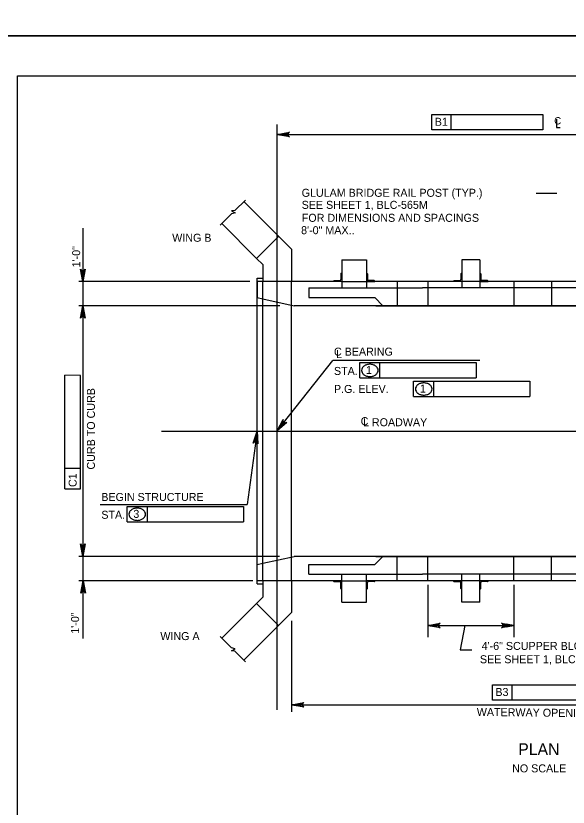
# Model space of a CAD drawing. Extents: x 638263 to 640391, y 293683 to 298655.
# Drawn here: x 638474.9 to 638681.9, y 297552.4 to 297849 of the extents above; entities that cross this region are included whole.
import ezdxf

# ---------------------------------------------------------------- set-up
doc = ezdxf.new("R2010")
doc.units = 0
for name, color, linetype in [('2', 7, 'Continuous'), ('3', 7, 'Continuous'), ('4', 7, 'Continuous'), ('PLT-BNDY', 7, 'Continuous')]:
    doc.layers.add(name, color=color, linetype=linetype)

msp = doc.modelspace()

# ---------------------------------------------------------------- linework, layer by layer
at = {"layer": '2'}
for p, q in [((638475.46, 297262.46), (638475.46, 297826.46)), ((638475.46, 297826.46), (639261.46, 297826.46)), ((638578.21, 297761.45), (638560.35, 297779.32)), ((638565.14, 297758.06), (638552.12, 297771.09)), ((638565.14, 297758.06), (638573.37, 297766.29)), ((638578.21, 297761.45), (638578.21, 297749.36)), ((638567.45, 297755.76), (638565.14, 297758.06)), ((638567.45, 297755.76), (638567.45, 297749.36)), ((638597.06, 297757.45), (638606.3, 297757.45)), ((638597.06, 297757.45), (638597.06, 297746.97)), ((638606.3, 297757.45), (638606.3, 297746.97)), ((638648.78, 297757.45), (638642.06, 297757.45)), ((638642.06, 297757.45), (638642.06, 297746.97)), ((638648.78, 297757.45), (638648.78, 297746.97)), ((638596.7, 297752.27), (638596.7, 297750.09)), ((638596.88, 297752.45), (638597.06, 297752.45)), ((638597.06, 297752.45), (638597.06, 297749.36)), ((638606.48, 297752.45), (638606.3, 297752.45)), ((638606.3, 297752.45), (638606.3, 297749.36)), ((638606.66, 297752.27), (638606.66, 297750.09)), ((638641.69, 297752.27), (638641.69, 297750.09)), ((638641.87, 297752.45), (638642.06, 297752.45)), ((638642.06, 297752.45), (638642.06, 297749.36)), ((638648.97, 297752.45), (638648.78, 297752.45)), ((638648.78, 297752.45), (638648.78, 297749.36)), ((638649.15, 297752.27), (638649.15, 297750.09)), ((638565.32, 297636.1), (638565.32, 297750.67)), ((638565.32, 297750.67), (638567.45, 297750.67)), ((638565.32, 297749.36), (638565.32, 297743.33)), ((638597.06, 297749.36), (638565.32, 297749.36)), ((638567.45, 297637.25), (638567.45, 297749.36)), ((638578.21, 297637.25), (638578.21, 297749.36)), ((638593.97, 297749.54), (638593.97, 297749.36)), ((638597.06, 297749.36), (638593.97, 297749.36)), ((638594.15, 297749.73), (638596.33, 297749.73)), ((638597.06, 297749.36), (638606.3, 297749.36)), ((638606.3, 297749.36), (638609.39, 297749.36)), ((638642.06, 297749.36), (638606.3, 297749.36)), ((638609.21, 297749.73), (638607.03, 297749.73)), ((638609.39, 297749.54), (638609.39, 297749.36)), ((638617.85, 297749.36), (638617.85, 297740.24)), ((638629.25, 297749.36), (638629.25, 297740.24)), ((638638.97, 297749.54), (638638.97, 297749.36)), ((638642.06, 297749.36), (638638.97, 297749.36)), ((638639.15, 297749.73), (638641.33, 297749.73)), ((638648.78, 297749.36), (638642.06, 297749.36)), ((638648.78, 297749.36), (638651.87, 297749.36)), ((638687.21, 297749.36), (638648.78, 297749.36)), ((638651.69, 297749.73), (638649.51, 297749.73)), ((638651.87, 297749.54), (638651.87, 297749.36)), ((638661.59, 297749.36), (638661.59, 297740.24)), ((638675.61, 297749.36), (638675.61, 297740.24)), ((638584.74, 297746.97), (638627.24, 297746.97)), ((638584.74, 297746.97), (638584.74, 297743.33)), ((638757.1, 297746.97), (638627.24, 297746.97)), ((638565.32, 297743.33), (638567.49, 297742.85)), ((638584.74, 297743.33), (638609.38, 297743.33)), ((638612.47, 297740.24), (638609.38, 297743.33)), ((638567.49, 297742.85), (638579.17, 297740.24)), ((638612.47, 297740.24), (638579.17, 297740.24)), ((638609.8, 297740.24), (638625.96, 297740.24)), ((638609.8, 297740.24), (638762.67, 297740.24)), ((638729.37, 297740.24), (638612.47, 297740.24)), ((638567.49, 297643.76), (638579.17, 297646.37)), ((638612.47, 297646.37), (638579.17, 297646.37)), ((638612.47, 297646.37), (638609.38, 297643.28)), ((638609.8, 297646.37), (638625.96, 297646.37)), ((638609.8, 297646.37), (638762.67, 297646.37)), ((638729.37, 297646.37), (638612.47, 297646.37)), ((638617.85, 297637.25), (638617.85, 297646.37)), ((638629.25, 297637.25), (638629.25, 297646.37)), ((638661.59, 297637.25), (638661.59, 297646.37)), ((638675.61, 297637.25), (638675.61, 297646.37)), ((638565.32, 297643.28), (638567.49, 297643.76)), ((638565.32, 297637.25), (638565.32, 297643.28)), ((638584.74, 297643.28), (638609.38, 297643.28)), ((638584.74, 297639.64), (638584.74, 297643.28)), ((638584.74, 297639.64), (638627.24, 297639.64)), ((638597.06, 297629.16), (638597.06, 297639.64)), ((638606.3, 297629.16), (638606.3, 297639.64)), ((638757.1, 297639.64), (638627.24, 297639.64)), ((638642.06, 297629.16), (638642.06, 297639.64)), ((638648.78, 297629.16), (638648.78, 297639.64)), ((638597.06, 297637.25), (638565.32, 297637.25)), ((638567.45, 297637.25), (638567.45, 297631.03)), ((638578.21, 297637.25), (638578.21, 297625.33)), ((638593.97, 297637.07), (638593.97, 297637.25)), ((638597.06, 297637.25), (638593.97, 297637.25)), ((638594.15, 297636.89), (638596.33, 297636.89)), ((638596.7, 297634.34), (638596.7, 297636.52)), ((638597.06, 297637.25), (638606.3, 297637.25)), ((638597.06, 297634.16), (638597.06, 297637.25)), ((638606.3, 297634.16), (638606.3, 297637.25)), ((638606.3, 297637.25), (638609.39, 297637.25)), ((638642.06, 297637.25), (638606.3, 297637.25)), ((638606.66, 297634.34), (638606.66, 297636.52)), ((638609.21, 297636.89), (638607.03, 297636.89)), ((638609.39, 297637.07), (638609.39, 297637.25)), ((638638.97, 297637.07), (638638.97, 297637.25)), ((638642.06, 297637.25), (638638.97, 297637.25)), ((638639.15, 297636.89), (638641.33, 297636.89)), ((638641.69, 297634.34), (638641.69, 297636.52)), ((638642.06, 297634.16), (638642.06, 297637.25)), ((638648.78, 297637.25), (638642.06, 297637.25)), ((638648.78, 297634.16), (638648.78, 297637.25)), ((638648.78, 297637.25), (638651.87, 297637.25)), ((638687.21, 297637.25), (638648.78, 297637.25)), ((638649.15, 297634.34), (638649.15, 297636.52)), ((638651.69, 297636.89), (638649.51, 297636.89)), ((638651.87, 297637.07), (638651.87, 297637.25)), ((638565.32, 297636.1), (638567.45, 297636.1)), ((638596.88, 297634.16), (638597.06, 297634.16)), ((638606.48, 297634.16), (638606.3, 297634.16)), ((638641.87, 297634.16), (638642.06, 297634.16)), ((638648.97, 297634.16), (638648.78, 297634.16)), ((638567.45, 297631.03), (638565.14, 297628.72)), ((638565.14, 297628.72), (638552.12, 297615.7)), ((638565.14, 297628.72), (638573.37, 297620.49)), ((638597.06, 297629.16), (638606.3, 297629.16)), ((638648.78, 297629.16), (638642.06, 297629.16)), ((638578.21, 297625.33), (638560.35, 297607.47))]:
    msp.add_line(p, q, dxfattribs=at)
for centre, radius, start, end in [((638596.88, 297752.27), 0.182, 90, 179.9984), ((638606.48, 297752.27), 0.182, 0.0016, 90), ((638641.87, 297752.27), 0.182, 90, 179.9984), ((638648.97, 297752.27), 0.182, 0.0016, 90), ((638594.15, 297749.54), 0.182, 90, 179.9984), ((638596.33, 297750.09), 0.364, 270, 359.9984), ((638607.03, 297750.09), 0.364, 180.0016, 270), ((638609.21, 297749.54), 0.182, 0.0016, 90), ((638639.15, 297749.54), 0.182, 90, 179.9984), ((638641.33, 297750.09), 0.364, 270, 359.9984), ((638649.51, 297750.09), 0.364, 180.0016, 270), ((638651.69, 297749.54), 0.182, 0.0016, 90), ((638594.15, 297637.07), 0.182, 180.0016, 270), ((638596.33, 297636.52), 0.364, 0.0016, 90), ((638607.03, 297636.52), 0.364, 90, 179.9984), ((638609.21, 297637.07), 0.182, 270, 359.9984), ((638639.15, 297637.07), 0.182, 180.0016, 270), ((638641.33, 297636.52), 0.364, 0.0016, 90), ((638649.51, 297636.52), 0.364, 90, 179.9984), ((638651.69, 297637.07), 0.182, 270, 359.9984), ((638596.88, 297634.34), 0.182, 180.0016, 270), ((638606.48, 297634.34), 0.182, 270, 359.9984), ((638641.87, 297634.34), 0.182, 180.0016, 270), ((638648.97, 297634.34), 0.182, 270, 359.9984)]:
    msp.add_arc(centre, radius, start, end, dxfattribs=at)
at = {"layer": '3'}
for p, q in [((638572.83, 297588.85), (638572.83, 297808.19)), ((638557.02, 297775.99), (638560.93, 297779.9)), ((638557.02, 297775.99), (638555.67, 297775.83)), ((638555.67, 297775.83), (638557.06, 297775.13)), ((638551.48, 297770.45), (638555.75, 297774.72)), ((638557.06, 297775.13), (638555.75, 297774.72)), ((638551.48, 297616.34), (638555.75, 297612.07)), ((638555.67, 297610.96), (638557.06, 297611.65)), ((638557.02, 297610.8), (638555.67, 297610.96)), ((638557.06, 297611.65), (638555.75, 297612.07)), ((638557.02, 297610.8), (638560.93, 297606.89))]:
    msp.add_line(p, q, dxfattribs=at)
at = {"layer": '4'}
for p, q in [((638630.83, 297811.98), (638638.06, 297811.98)), ((638630.83, 297806.21), (638630.83, 297811.98)), ((638638.06, 297806.21), (638638.06, 297811.98)), ((638638.06, 297811.98), (638672.35, 297811.98)), ((638672.35, 297811.98), (638672.35, 297806.21)), ((638677.52, 297810.26), (638677.52, 297807.07)), ((638672.35, 297806.21), (638630.83, 297806.21)), ((638677.52, 297807.07), (638678.85, 297807.07)), ((638572.83, 297804.47), (638769.01, 297804.47)), ((638669.92, 297782.54), (638677.65, 297782.54)), ((638499.98, 297769.4), (638499.98, 297615.55)), ((638562.63, 297749.36), (638498.54, 297749.36)), ((638573.85, 297740.24), (638498.54, 297740.24)), ((638572.83, 297693.42), (638593.74, 297719.75)), ((638648.82, 297719.75), (638593.74, 297719.75)), ((638603.79, 297718.99), (638611.37, 297718.99)), ((638603.79, 297713.22), (638603.79, 297718.99)), ((638611.37, 297713.22), (638611.37, 297718.99)), ((638611.37, 297718.99), (638647.38, 297718.99)), ((638647.38, 297718.99), (638647.38, 297713.22)), ((638499.15, 297714.21), (638493.24, 297714.22)), ((638493.24, 297679.26), (638493.24, 297714.22)), ((638499.15, 297671.69), (638499.15, 297714.21)), ((638603.79, 297713.22), (638647.38, 297713.22)), ((638623.98, 297706.25), (638623.98, 297712.02)), ((638623.98, 297712.02), (638631.56, 297712.02)), ((638631.56, 297706.25), (638631.56, 297712.02)), ((638631.56, 297712.02), (638667.57, 297712.02)), ((638667.57, 297712.02), (638667.57, 297706.25)), ((638623.98, 297706.25), (638667.57, 297706.25)), ((638529.5, 297693.31), (638814.51, 297693.31)), ((638565.32, 297693.31), (638561.63, 297665.85)), ((638493.24, 297671.7), (638493.24, 297679.26)), ((638499.15, 297679.25), (638493.24, 297679.26)), ((638493.24, 297671.7), (638499.15, 297671.69)), ((638506.55, 297665.85), (638561.63, 297665.85)), ((638516.6, 297659.32), (638516.6, 297665.08)), ((638516.6, 297665.08), (638524.18, 297665.08)), ((638524.18, 297659.32), (638524.18, 297665.08)), ((638524.18, 297665.08), (638560.19, 297665.08)), ((638560.19, 297665.08), (638560.19, 297659.32)), ((638516.6, 297659.32), (638560.19, 297659.32)), ((638573.69, 297646.37), (638498.54, 297646.37)), ((638563.75, 297637.25), (638498.54, 297637.25)), ((638629.25, 297635.71), (638629.25, 297616.07)), ((638661.59, 297635.71), (638661.59, 297616.07)), ((638578.21, 297622.15), (638578.21, 297588.05)), ((638629.25, 297620.5), (638661.59, 297620.5)), ((638643.2, 297620.5), (638641.36, 297611.28)), ((638641.36, 297611.28), (638645.79, 297611.28)), ((638653.55, 297592.5), (638653.56, 297598.27)), ((638653.56, 297598.27), (638660.91, 297598.27)), ((638660.9, 297592.5), (638660.91, 297598.27)), ((638660.91, 297598.27), (638695.08, 297598.25)), ((638695.08, 297592.48), (638653.55, 297592.5)), ((638578.21, 297590.75), (638763.2, 297590.75))]:
    msp.add_line(p, q, dxfattribs=at)
for points in [[(638572.83, 297804.47), (638577.49, 297805.34), (638577.13, 297805.1), (638576.95, 297804.78), (638576.89, 297804.47), (638576.95, 297804.16), (638577.13, 297803.85), (638577.49, 297803.6), (638572.83, 297804.47), (638577.13, 297803.85), (638576.95, 297804.16), (638572.83, 297804.47), (638576.89, 297804.47), (638576.95, 297804.78), (638572.83, 297804.47), (638577.13, 297805.1)], [(638499.98, 297749.36), (638499.11, 297754.02), (638499.36, 297753.67), (638499.67, 297753.48), (638499.98, 297753.43), (638500.3, 297753.48), (638500.61, 297753.67), (638500.86, 297754.02), (638499.98, 297749.36), (638500.61, 297753.67), (638500.3, 297753.48), (638499.98, 297749.36), (638499.98, 297753.43), (638499.67, 297753.48), (638499.98, 297749.36), (638499.36, 297753.67)], [(638499.98, 297740.24), (638500.86, 297735.58), (638500.61, 297735.94), (638500.3, 297736.12), (638499.98, 297736.18), (638499.67, 297736.12), (638499.36, 297735.94), (638499.11, 297735.58), (638499.98, 297740.24), (638499.36, 297735.94), (638499.67, 297736.12), (638499.98, 297740.24), (638499.98, 297736.18), (638500.3, 297736.12), (638499.98, 297740.24), (638500.61, 297735.94)], [(638572.83, 297693.42), (638575.04, 297697.61), (638575.02, 297697.17), (638575.14, 297696.83), (638575.36, 297696.6), (638575.63, 297696.45), (638575.99, 297696.4), (638576.41, 297696.52), (638572.83, 297693.42), (638575.99, 297696.4), (638575.63, 297696.45), (638572.83, 297693.42), (638575.36, 297696.6), (638575.14, 297696.83), (638572.83, 297693.42), (638575.02, 297697.17)], [(638565.32, 297693.31), (638565.56, 297688.57), (638565.36, 297688.96), (638565.08, 297689.19), (638564.78, 297689.28), (638564.46, 297689.27), (638564.13, 297689.13), (638563.83, 297688.8), (638565.32, 297693.31), (638564.13, 297689.13), (638564.46, 297689.27), (638565.32, 297693.31), (638564.78, 297689.28), (638565.08, 297689.19), (638565.32, 297693.31), (638565.36, 297688.96)], [(638499.98, 297646.37), (638499.11, 297651.03), (638499.36, 297650.67), (638499.67, 297650.48), (638499.98, 297650.43), (638500.3, 297650.48), (638500.61, 297650.67), (638500.86, 297651.03), (638499.98, 297646.37), (638500.61, 297650.67), (638500.3, 297650.48), (638499.98, 297646.37), (638499.98, 297650.43), (638499.67, 297650.48), (638499.98, 297646.37), (638499.36, 297650.67)], [(638500.09, 297637.25), (638500.97, 297632.59), (638500.72, 297632.95), (638500.41, 297633.13), (638500.09, 297633.19), (638499.78, 297633.13), (638499.47, 297632.95), (638499.22, 297632.59), (638500.09, 297637.25), (638499.47, 297632.95), (638499.78, 297633.13), (638500.09, 297637.25), (638500.09, 297633.19), (638500.41, 297633.13), (638500.09, 297637.25), (638500.72, 297632.95)], [(638629.25, 297620.5), (638633.91, 297621.38), (638633.55, 297621.13), (638633.37, 297620.82), (638633.31, 297620.5), (638633.37, 297620.19), (638633.55, 297619.88), (638633.91, 297619.63), (638629.25, 297620.5), (638633.55, 297619.88), (638633.37, 297620.19), (638629.25, 297620.5), (638633.31, 297620.5), (638633.37, 297620.82), (638629.25, 297620.5), (638633.55, 297621.13)], [(638661.59, 297620.5), (638656.93, 297619.63), (638657.29, 297619.88), (638657.47, 297620.19), (638657.53, 297620.5), (638657.47, 297620.82), (638657.29, 297621.13), (638656.93, 297621.38), (638661.59, 297620.5), (638657.29, 297621.13), (638657.47, 297620.82), (638661.59, 297620.5), (638657.53, 297620.5), (638657.47, 297620.19), (638661.59, 297620.5), (638657.29, 297619.88)], [(638578.21, 297590.75), (638582.87, 297591.62), (638582.52, 297591.38), (638582.33, 297591.06), (638582.28, 297590.75), (638582.33, 297590.44), (638582.52, 297590.13), (638582.87, 297589.88), (638578.21, 297590.75), (638582.52, 297590.13), (638582.33, 297590.44), (638578.21, 297590.75), (638582.28, 297590.75), (638582.33, 297591.06), (638578.21, 297590.75), (638582.52, 297591.38)]]:
    msp.add_lwpolyline(points, dxfattribs=at)
for points in [[(638499.5, 297752.25), (638500.46, 297752.25), (638499.98, 297749.36)], [(638499.5, 297737.36), (638500.46, 297737.36), (638499.98, 297740.24)], [(638499.5, 297649.25), (638500.46, 297649.25), (638499.98, 297646.37)], [(638499.5, 297634.38), (638500.46, 297634.38), (638499.98, 297637.26)], [(638632.2, 297621), (638632.2, 297620.01), (638629.25, 297620.5)], [(638658.64, 297621), (638658.64, 297620.01), (638661.59, 297620.5)]]:
    msp.add_lwpolyline(points, close=True, dxfattribs=at)
for centre, radius, start, end in [((638606.17, 297716.06), 1.71, 150.6308, 180), ((638606.85, 297715.68), 2.49, 126.3544, 150.6308), ((638607.29, 297715.08), 3.23, 106.9552, 126.3544), ((638607.58, 297714.13), 4.22, 90, 106.9552), ((638607.58, 297714.13), 4.22, 73.0448, 90), ((638607.87, 297715.08), 3.23, 53.6456, 73.0448), ((638608.31, 297715.68), 2.49, 29.3692, 53.6456), ((638608.99, 297716.06), 1.71, 0, 29.3692), ((638606.17, 297716.06), 1.71, 180, 209.3692), ((638606.85, 297716.44), 2.49, 209.3692, 233.6456), ((638607.29, 297717.04), 3.23, 233.6456, 253.0448), ((638607.58, 297717.98), 4.22, 253.0448, 270), ((638607.58, 297717.98), 4.22, 270, 286.9552), ((638607.87, 297717.04), 3.23, 286.9552, 306.3544), ((638608.31, 297716.44), 2.49, 306.3544, 330.6308), ((638608.99, 297716.06), 1.71, 330.6308, 0), ((638627.04, 297708.71), 2.49, 126.3544, 150.6308), ((638627.48, 297708.11), 3.23, 106.9552, 126.3544), ((638627.77, 297707.16), 4.22, 90, 106.9552), ((638627.77, 297707.16), 4.22, 73.0448, 90), ((638628.06, 297708.11), 3.23, 53.6456, 73.0448), ((638628.5, 297708.71), 2.49, 29.3692, 53.6456), ((638626.36, 297709.09), 1.71, 150.6308, 180), ((638626.36, 297709.09), 1.71, 180, 209.3692), ((638627.04, 297709.47), 2.49, 209.3692, 233.6456), ((638628.5, 297709.47), 2.49, 306.3544, 330.6308), ((638629.17, 297709.09), 1.71, 0, 29.3692), ((638629.17, 297709.09), 1.71, 330.6308, 0), ((638627.48, 297710.07), 3.23, 233.6456, 253.0448), ((638627.77, 297711.02), 4.22, 253.0448, 270), ((638627.77, 297711.02), 4.22, 270, 286.9552), ((638628.06, 297710.07), 3.23, 286.9552, 306.3544), ((638519.66, 297661.77), 2.49, 126.3544, 150.6308), ((638520.1, 297661.17), 3.23, 106.9552, 126.3544), ((638520.39, 297660.23), 4.22, 90, 106.9552), ((638520.39, 297660.23), 4.22, 73.0448, 90), ((638520.67, 297661.17), 3.23, 53.6456, 73.0448), ((638521.12, 297661.77), 2.49, 29.3692, 53.6456), ((638518.98, 297662.15), 1.71, 150.6308, 180), ((638518.98, 297662.15), 1.71, 180, 209.3692), ((638519.66, 297662.53), 2.49, 209.3692, 233.6456), ((638520.1, 297663.13), 3.23, 233.6456, 253.0448), ((638520.67, 297663.13), 3.23, 286.9552, 306.3544), ((638521.12, 297662.53), 2.49, 306.3544, 330.6308), ((638521.79, 297662.15), 1.71, 0, 29.3692), ((638521.79, 297662.15), 1.71, 330.6308, 0), ((638520.39, 297664.08), 4.22, 253.0448, 270), ((638520.39, 297664.08), 4.22, 270, 286.9552)]:
    msp.add_arc(centre, radius, start, end, dxfattribs=at)
at = {"layer": 'PLT-BNDY'}
for points in [[(638435.46, 298435.46), (639276.46, 298435.46), (639276.46, 297841.46), (638435.46, 297841.46)], [(638435.46, 297841.46), (639276.46, 297841.46), (639276.46, 297247.46), (638435.46, 297247.46)]]:
    msp.add_lwpolyline(points, close=True, dxfattribs=at)

# ---------------------------------------------------------------- texts
at = {"layer": '4'}
for s, height, p in [('B1', 3, (638631.9, 297807.74)), ('C', 2.73, (638676.65, 297808.25)), ('GLULAM BRIDGE RAIL POST (TYP.)', 3, (638582.01, 297781.13)), ('SEE SHEET 1, BLC-565M', 3, (638582.01, 297776.61)), ('FOR DIMENSIONS AND SPACINGS', 3, (638582.07, 297771.75)), ('8\'-0" MAX..', 3, (638581.8, 297767.11)), ('WING B', 3, (638533.5, 297764.28)), ('C BEARING', 3, (638594.12, 297721.59)), ('L', 3, (638594.94, 297720.68)), ('STA.', 3, (638594.12, 297714.36)), ('1', 3, (638606.13, 297714.71)), ('P.G. ELEV.', 3, (638594.12, 297707.61)), ('1', 3, (638626.32, 297707.74)), ('C', 3, (638604.13, 297695.53)), ('L ROADWAY', 3, (638605, 297695.13)), ('BEGIN STRUCTURE', 3, (638506.93, 297667.12)), ('STA.', 3, (638506.93, 297660.45)), ('3', 3, (638518.93, 297660.8)), ('WING A', 3, (638529.05, 297614.98)), ('4\'-6" SCUPPER BLOCK (TYP.)', 3, (638649.46, 297611.29)), ('SEE SHEET 1, BLC-565M', 3, (638648.82, 297606.3)), ('PLAN', 4.429, (638663.17, 297571.87)), ('NO SCALE', 3, (638660.9, 297565.4))]:
    msp.add_text(s, height=height, dxfattribs=at).set_placement(p)
for s, rotation, p in [('1\'-0"', 90, (638499.01, 297754.67)), ('CURB TO CURB', 90, (638504.54, 297678.9)), ('C1', 89.9382, (638497.69, 297672.35)), ('1\'-0"', 90, (638498.6, 297617.36)), ('B3', 359.9692, (638654.62, 297594.03)), ('WATERWAY OPENING', 359.308, (638647.63, 297586.58))]:
    msp.add_text(s, height=3, rotation=rotation, dxfattribs=at).set_placement(p)

doc.saveas('drawing.dxf')
